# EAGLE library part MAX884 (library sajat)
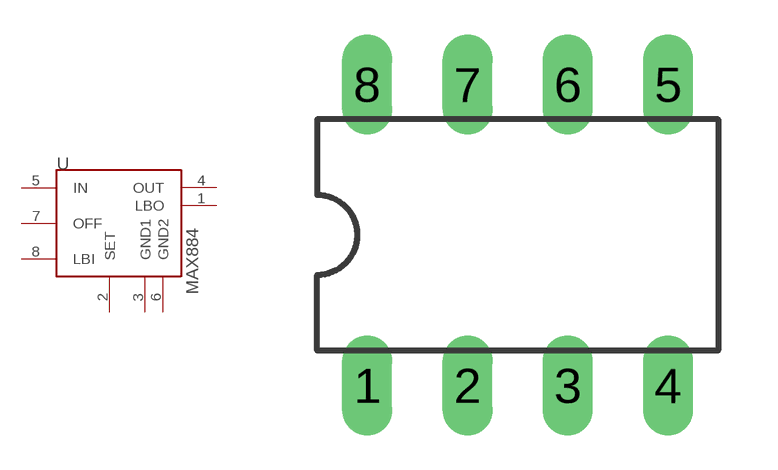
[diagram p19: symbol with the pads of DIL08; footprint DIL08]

Designator prefix -

## MAX884  [DIL08]
1  LBO
2  SET
3  GND1
4  OUT
5  IN
6  GND2
7  OFF
8  LBI

## Footprint DIL08 (pad centres in mm)
Dual In Line Package
drill 0.5 pad 1.27 long: 1 -3.81,-3.81; 2 -1.27,-3.81; 3 1.27,-3.81; 4 3.81,-3.81; 5 3.81,3.81; 6 1.27,3.81; 7 -1.27,3.81; 8 -3.81,3.81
